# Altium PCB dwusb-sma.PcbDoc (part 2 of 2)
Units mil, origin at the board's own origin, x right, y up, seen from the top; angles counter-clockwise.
Board outline 1415 x 748.03 mil, 4 copper layers (Component Side, Ground Plane, Power Plane, Solder Side), stack 62.214 mil thick; 104 components, 67 nets, 356 pads, 248 vias.
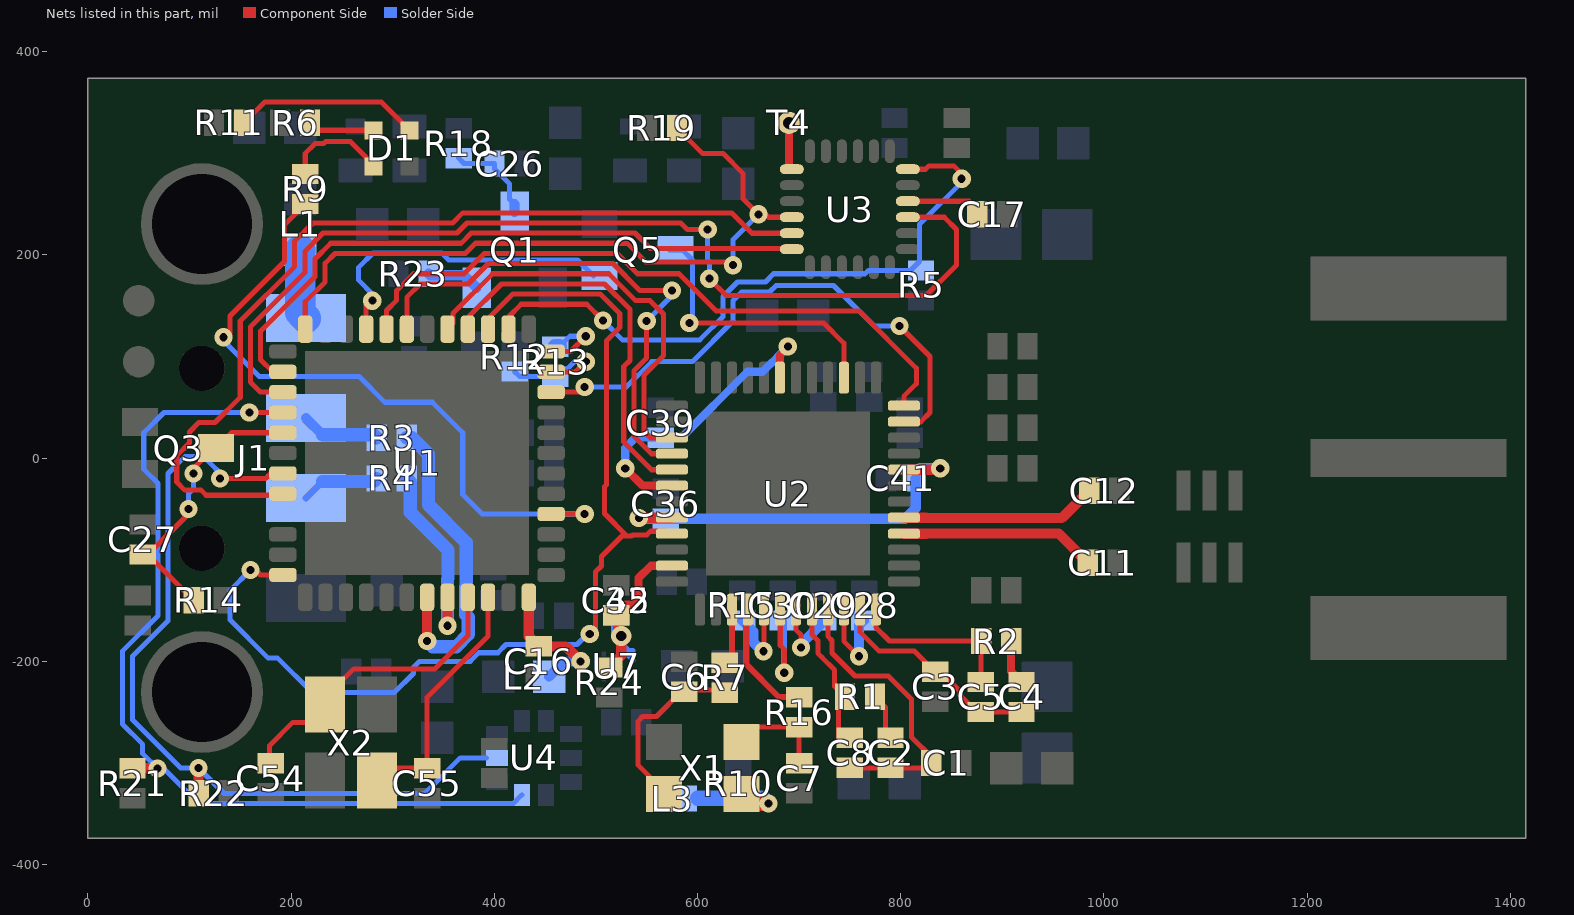
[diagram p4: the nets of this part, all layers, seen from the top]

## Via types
v1: diameter 18, hole 8, Component Side to Solder Side, tented both sides, 165 vias
v2: diameter 18, hole 8, Component Side to Solder Side, 78 vias
v3: diameter 20, hole 10, Component Side to Solder Side, tented both sides, 2 vias
v4: diameter 25, hole 12, Component Side to Solder Side, 2 vias
v5: diameter 22, hole 10, Component Side to Solder Side, tented both sides, 1 vias

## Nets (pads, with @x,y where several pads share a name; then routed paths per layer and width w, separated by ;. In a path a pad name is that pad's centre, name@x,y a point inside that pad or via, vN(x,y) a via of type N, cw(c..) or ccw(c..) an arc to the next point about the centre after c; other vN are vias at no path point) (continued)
LPS25-SCL: R21.1 U1.28 U4.2 | length 922.4
  Component Side w5: v1(68.52,-305.42) v1@68.7,-305.24 ; v1(158.94,45) U1.28@191.94,45 ; v1@68.7,-305.24 68.94,-305 73.94,-305 73.7,-305.24 v1@68.7,-305.24
  Component Side w10: R21.1@43.94,-305.24 v1@68.7,-305.24
  Solder Side w5: v1(158.94,45) 75,45 55,25 55,-10.86 68.94,-24.79 68.94,-155 33.94,-190 33.94,-261.65 53.94,-281.65 53.94,-290.84 v1(68.52,-305.42) 74.56,-305.42 109.14,-340 418.54,-340 U4.2@427.13,-331.42
LPS25-SDA: R22.1 U1.31 U4.4 | length 859.1
  Component Side w5: v2(130,-20) 175,-20 ; 148.94,-20 175,-20 ; 175,-20 177.22,-17.78 ; 177.22,-17.78 189.16,-17.78 U1.31@191.94,-15 180,-15 177.22,-17.78
  Component Side w10: v1(108.94,-305) 108.94,-329.76 R22.1@109.17,-330
  Solder Side w5: v2(130,-20) 135.56,-20 115.56,0 112.27,0 110.77,1.5 95.44,1.5 78.94,-15 78.94,-160 43.94,-195 43.94,-257.51 91.43,-305 v1(108.94,-305) 133.94,-330 331.54,-330 366.54,-295 U4.4@392.52,-295
MPU-CS#: R19.1 U1.24 U3.22 | length 714
  Component Side w5: U1.24@213.94,127 213.94,153.94 233.5,173.5 233.5,191.83 243.17,201.5 371.5,201.5 381.5,211.5 530.77,211.5 549.1,193.17 631.83,193.17 v2(635,190) ; R19.1@579.76,325 604.76,300 625,300 645,280 645,255 v2(660,240) ; v2@663.5,243.5 669.87,237.13 U3.22@692.91,237.13
  Solder Side w5: v2(635,190) 635,215 v2(660,240)
MPU-INT: R5.1 U1.14 U3.12 | length 640.3
  Component Side w5: U1.14@413.94,127 413.94,138.94 426.5,151.5 491.03,151.5 v2@506.5,136.03 ; U3.12@807.09,284.37 824.37,284.37 827.74,287.74 852.26,287.74 860,280 v2(860,275)
  Solder Side w5: v2(507,135.53) 526.03,116.5 602.36,116.5 625,139.14 625,159.14 639.36,173.5 666.83,173.5 674.83,181.5 765,181.5 768.26,184.76 809.76,184.76 818.5,193.5 818.5,230.17 860,271.67 v2(860,275)
MPU-SCK: U1.32 U3.23 | length 914.2
  Component Side w5: U1.32@191.94,-35 190.44,-36.5 116.5,-36.5 111.5,-31.5 95.44,-31.5 87.44,-23.5 87.44,2.44 100,15 100,25.76 109.24,35 125,35 149.94,59.94 149.94,134.94 203.5,188.5 203.5,213.5 221.5,231.5 359.07,231.5 369.07,241.5 633.5,241.5 653.62,221.38 U3.23@692.91,221.38
MPU-SDI: U1.26 U3.24 | length 635.2
  Component Side w5: U1.26@191.94,85 181.88,85 169.94,96.94 169.94,124.94 223.5,178.5 223.5,195.98 239.02,211.5 367.36,211.5 377.36,221.5 538.5,221.5 553.5,206.5 692.91,206.5 U3.24@692.91,205.63
MPU-SDO: U1.27 U3.9 | length 997.2
  Component Side w5: U1.27@191.94,65 170,65 159.94,75.06 159.94,129.08 213.5,182.64 213.5,203.5 231.5,221.5 363.22,221.5 373.22,231.5 583.5,231.5 590,225 v2(610,225) ; v2(611.67,176.67) 628.33,160 825,160 855,190 855,225 842.87,237.13 U3.9@807.09,237.13
  Solder Side w5: v2(610,225) 610,195 611.67,193.33 v2(611.67,176.67)
NetC2_2: C2.2 R1.2 | length 44.5
  Component Side w5: R1.2@774.76,-235 785,-245.24 C2.2@785,-275.24
NetC4_2: C4.2 R2.1 | length 44.5
  Component Side w8: R2.1@908.7,-180 908.7,-210 C4.2@918.94,-220.24
NetC5_2: C5.2 R2.2 U2.12 | length 166.9
  Component Side w5: U2.12@775.55,-149.17 775.55,-166.61 788.94,-180 R2.2@879.17,-180 878.94,-180.24 C5.2@878.94,-220.24
NetC6_2: C6.2 R7.2 X1.3 | length 182.3
  Component Side w5: X1.3@566.81,-330.59 566.81,-327.35 541.59,-302.14 541.59,-258.59 545.99,-254.19 559.57,-254.19 584,-229.76 C6.2@587,-229.76 588,-230.76 595.67,-230.76 598.17,-228.26 624.5,-228.26 R7.2@627,-230.76
NetC7_2: C7.2 R16.2 X1.1 | length 103.6
  Component Side w5: X1.1@638.19,-280 653.43,-264.76 R16.2@700,-264.76 C7.2@700,-300.24
NetC8_1: C8.1 R1.1 U2.8 | length 139.4
  Component Side w5: U2.8@712.56,-149.17 712.56,-173.62 718.44,-179.5 718.44,-191.98 722.44,-195.98 735,-208.54 735,-224.76 R1.1@745.24,-235 ; C8.1@738.94,-275.24 R1.1@738.94,-235.24
NetC17_1: C17.1 U3.10 | length 78.5
  Component Side w5: U3.10@807.09,252.87 867.36,252.87 C17.1@880.24,240
NetC26_1: C26.1 Q1.3 R18.2 | length 93.2
  Solder Side w5: R18.2@365,295.24 370.24,290 C26.1@400.24,290 400.24,284.76 415,270 415,255 Q1.3@420,250
  Solder Side w10: Q1.3@420,242.4 Q1.3@420,250
NetD1_2: D1.2 R9.2 | length 103.2
  Component Side w5: R9.2@213.94,279.76 213.94,300 223.44,309.5 231.81,309.5 233.81,311.5 258.5,311.5 281.22,288.78 D1.2@281.22,287.28
NetD1_3: D1.3 R6.2 | length 54.8
  Component Side w5: R6.2@226.42,322.72 D1.3@281.22,322.72
NetD1_4: D1.4 R11.2 | length 183
  Component Side w5: R11.2@153.7,330 174.2,350.5 288.87,350.5 D1.4@316.65,322.72
NetL3_2: L3.2 R10.2 X1.4 | length 102.9
  Component Side w15: X1.4@643.19,-330.59 645.59,-330.59 655,-340 v1(670,-340)
  Solder Side w15: 600,-334.76 R10.2@640,-334.76 664.76,-334.76 v1(670,-340)
NetQ1_2: Q1.2 R23.2 | length 55.1
  Solder Side w5: R23.2@334.76,180 R23.2@336.7,180
  Solder Side w10: R23.2@335.2,181.5 336.7,180 370.2,180 Q1.2@382.6,167.6
NetR15_2: R15.2 U2.5 | length 83.3
  Component Side w5: v2(665,-190) 665,-191.06 665.32,-191.38 U2.5@665.32,-149.17
  Solder Side w10: R15.2@643.94,-159.76 655,-170.83 655,-181.06 663.94,-190 v2(665,-190)
NetT4_1: T4.1 U3.19 | length 46.8
  Component Side w8: T4.1@690,330 690,287.28 U3.19@692.91,284.37
RED-LED: R9.1 U1.4 | length 666
  Component Side w5: v2(133.44,118.97) 135,117.41 139.94,122.34 139.94,139.94 193.5,193.5 193.5,229.8 R9.1@213.94,250.24 ; U1.4@455.94,-55 v2(488.94,-55)
  Solder Side w5: v2(133.44,118.97) 133.44,115.5 168.44,80.49 266.83,80.49 292.32,55 338.94,55 368.94,25 368.94,-35.86 388.08,-55 v2(488.94,-55)
RESET#: Q5.3 U2.27 | length 284.3
  Component Side w5: v1(592,133) 724.27,133 744.06,113.22 U2.27@744.06,79.17
  Solder Side w5: Q5.3@572.4,205 585,205 595,195 595,136 v1(592,133)
RF-CS#: U1.20 U2.24 | length 657.6
  Component Side w5: U1.20@293.94,127 293.94,145.36 303.94,155.36 303.94,165 320.44,181.5 370.1,181.5 390.1,201.5 520.93,201.5 540.93,181.5 581.83,181.5 618.33,145 758.94,145 815.44,88.5 815.44,73.17 803.11,60.84 U2.24@803.11,51.61
RF-IRQ: U1.15 U1.36 U2.45 | length 1055.6
  Component Side w5: v2(160,-110) 165,-110 170,-115 U1.36@191.94,-115 ; U1.15@393.94,127 393.94,137.37 418.07,161.5 504.36,161.5 523.5,142.36 523.5,128.69 510.44,115.63 510.44,-26.23 508.5,-28.17 508.5,-54.56 530.44,-76.5 ; v2(494,-173) 497,-173 498,-172 499.5,-170.5 499.5,-112.13 505.44,-106.19 505.44,-96.83 525.77,-76.5 530.44,-76.5 ; U2.45@569.76,-74.37 567.31,-71.92 553.69,-71.92 550.11,-75.5 546.45,-75.5 536.09,-75.5 535.09,-76.5 530.44,-76.5
  Solder Side w5: v2(160,-110) 140,-130 140,-159.4 177.1,-196.5 186.5,-196.5 220.5,-230.5 301.81,-230.5 320.44,-211.87 320.44,-205.89 326.33,-200 376.33,-200 384.83,-191.5 403.5,-191.5 411.5,-183.5 481.5,-183.5 494,-171 v2(494,-173)
RF-MISO: U1.19 U2.40 | length 515.5
  Component Side w5: U1.19@313.94,127 313.94,158.33 327.1,171.5 374.24,171.5 394.24,191.5 516.79,191.5 543.29,165 v2(575,165) ; v2(550,135) 550,98.54 537.44,85.98 537.44,21.61 554.68,4.37 U2.40@569.76,4.37
  Solder Side w5: v2(550,135) 575,160 v2(575,165)
RF-MOSI: U1.17 U2.39 | length 410.7
  Component Side w5: U1.17@353.94,127 359.44,132.5 359.44,142.56 398.38,181.5 512.65,181.5 539.15,155 553.33,155 566.5,141.83 566.5,100.9 547.44,81.83 547.44,26.5 553.82,20.12 U2.39@574.76,20.12
RF-RESET: Q5.1 U1.21 | length 308.8
  Component Side w5: U1.21@273.94,127 v1@273.94,150 ; v1@278.94,155 v1(280,155)
  Solder Side w5: v1(280,155) 280,161.67 266.5,175.17 266.5,187.83 280.67,202 348.31,202 355.21,195.1 481.91,195.1 Q5.1@497.6,179.41
RF-SCLK: U1.16 U2.41 | length 381.8
  Component Side w5: U1.16@373.94,127 373.94,138.44 407,171.5 508.5,171.5 533.5,146.5 533.5,96.18 527.44,90.12 527.44,15.86 554.68,-11.38 U2.41@569.76,-11.38
RF-WAKE-UP: U1.10 U2.23 | length 541.8
  Component Side w5: U1.10@455.94,65 483.94,65 v2(488.94,70) ; v2(798.94,130) 828.94,100 828.94,45 819.8,35.87 U2.23@803.11,35.87
  Solder Side w5: v2(488.94,70) 530,70 555,95 595,95 635,135 635,155 643.5,163.5 670.98,163.5 677.48,170 733.94,170 773.94,130 v2(798.94,130)
RF_N: C12.1 U2.17 | length 193.7
  Component Side w9.96: U2.17@803.11,-58.62 825,-58.62 825.39,-59.02 958.46,-59.02 C12.1@985.47,-32.01
RF_P: C11.1 U2.16 | length 193.2
  Component Side w9.96: U2.16@803.11,-74.37 825,-74.37 825.39,-73.98 955.28,-73.98 C11.1@984.17,-102.87
SAM-RESET#: C27.1 Q3.3 R14.1 U1.29 | length 264.7
  Component Side w5: v2@98.94,-55 59.17,-94.76 59.17,-95 R14.1@104.17,-140 ; v1(103.94,-15) 103.94,-10 123.94,10 Q3.3@126.34,10 141.34,25 U1.29@191.94,25
  Solder Side w5: v2(98.94,-50) 98.94,-35 103.94,-30 v1(103.94,-15)
USB-DATA_N: J1.2 R3.2 | length 77.6
  Solder Side w10: J1.2@214.57,39.37 J1.2@230.94,23
  Solder Side w13.07: J1.2@230.94,23 281.17,23 R3.2@284.17,20
USB-DATA_P: J1.3 R4.2 | length 77.6
  Solder Side w7: J1.3@214.57,-39.37 J1.3@230.94,-23
  Solder Side w13.07: J1.3@230.94,-23 281.17,-23 R4.2@284.17,-20
USB_N: R3.1 U1.43 | length 313
  Component Side w10: v2(333.94,-180) U1.43@333.94,-137
  Solder Side w13.07: R3.1@313.7,20 319,20 335.24,3.76 335.24,-45.74 372.54,-83.05 372.54,-125.95 372.01,-126.48 372.01,-154.03 374.47,-156.49 374.47,-173.51 362.44,-185.54 339.47,-185.54 v2(333.94,-180)
USB_P: R4.1 U1.44 | length 190.1
  Component Side w10: v1(353.94,-165) U1.44@353.94,-137
  Solder Side w13.07: R4.1@313.7,-20 317.17,-23.47 317.17,-53.23 354.47,-90.53 354.47,-118.47 353.94,-119 v1(353.94,-165)
VDDBATT: C35.1 C42.1 R24.2 U2.47 U7.1 | length 201.7
  Component Side w8: C35.1@522,-156.76 522,-150.76 528.53,-144.24 536.73,-144.24 541.36,-139.6 542,-138.96 542,-118 554.13,-105.87 U2.47@574.76,-105.87
  Component Side w10: R24.2@513.31,-205.98 525,-194.29 v3(525,-175) v3@520.24,-175 ; v3@520,-174.76 522,-176.76 522,-156.76 C35.1@520,-154.76
  Solder Side w8: v3(525,-175) 525,-184.25 530,-189.25 530,-190.39 U7.1@532.3,-192.7
  Solder Side w10: C42.1@520,-154.76 520,-174.76 520.24,-175 v3(525,-175)
VDDCLK: C1.2 C2.1 C8.2 U2.9 | length 299.5
  Component Side w5: U2.9@728.31,-149.17 728.31,-175.23 732.44,-179.36 732.44,-191.83 755.1,-214.5 787.87,-214.5 810.5,-237.13 810.5,-274.45 830.24,-294.19 C1.2@830.24,-300 825.47,-304.76 C2.1@790,-304.76 C8.2@750,-304.76 C8.2@745,-304.76
VDDIF: C29.1 U2.7 | length 75
  Component Side w5: U2.7@696.81,-149.17 696.81,-168.81 701.94,-173.94 v2(701.94,-186.33)
  Solder Side w5: C29.1@723.94,-161.06 C29.1@723.94,-159.76
  Solder Side w10: v2(701.94,-186.33) 701.94,-183.06 C29.1@723.94,-161.06
VDDIO: C39.1 U2.31 U2.42 | length 303.7
  Component Side w8: v2(528.94,-10) 545.94,-27 569.64,-27 U2.42@569.76,-27.13 ; U2.31@681.06,79.17 681.06,101.67 688.94,109.54 v1(688.94,110)
  Solder Side w8: v2(528.94,-10) 528.94,10 539.17,20.24 C39.1@563.94,20.24 584.17,20.24 648.94,85 663.94,85 672.32,93.38 672.77,93.38 683.32,103.92 683.32,104.38 v1(688.94,110)
VDDMS: C30.1 U2.6 | length 116.7
  Component Side w5: U2.6@681.06,-149.17 681.5,-149.61 681.5,-184.23 685.44,-188.17 v2(685.44,-211.24)
  Solder Side w5: C30.1@683.94,-159.76 685.2,-159.76 685.44,-160 v2(685.44,-211.24)
VDDPLL: C16.1 L2.2 U1.48 | length 136.8
  Component Side w10: U1.48@433.94,-137 433.94,-175.24 C16.1@443.94,-185.24 470.24,-185.24 v2(485,-200)
  Solder Side w10: L2.2@453.94,-215 468.94,-200 v2(485,-200)
VDDREG: C36.1 C41.1 U2.20 U2.44 | length 412.3
  Component Side w10: v1(542.27,-59) 539.94,-59 539.33,-59.61 540.32,-58.62 U2.44@574.76,-58.62 ; U2.20@803.11,-11.38 837.56,-11.38 v1(838.94,-10)
  Solder Side w10: v1(542.27,-59) 542.88,-59.61 803.54,-59.61 803.94,-60 814.76,-49.17 C41.1@814.76,-20 ; C41.1@817.87,-20 817.87,-11.38 819.25,-10 v1(838.94,-10)
VDDSYN: C28.1 U2.10 | length 89.3
  Component Side w5: U2.10@744.06,-149.17 744.06,-180.12 v2(758.94,-195)
  Solder Side w10: v2(758.94,-195) 758.94,-164.76 C28.1@763.94,-159.76
VDDVCO: C3.1 C4.1 C5.1 U2.11 | length 215.8
  Component Side w5: U2.11@759.8,-149.17 759.8,-170.87 778.94,-190 813.7,-190 C3.1@833.94,-210.24 839.17,-210.24 858.44,-229.5 858.44,-233.34 874.86,-249.76 C5.1@878.94,-249.76 C4.1@918.94,-249.76
VERSION-SENSE: R12.1 R13.2 U1.11 | length 116.4
  Component Side w5: U1.11@455.94,85 480,85 v2(490,95)
  Solder Side w5: R12.1@420,85.24 425,80.24 R13.2@460,80.24 464.08,80.24 478.84,95 v2(490,95)
VERSION-SENSE-EN#: R13.1 U1.12 | length 74.5
  Component Side w5: U1.12@455.94,105 475,105 v2(490,120)
  Solder Side w5: R13.1@464.11,109.76 474.34,120 v2(490,120)
  Solder Side w15: R13.1@460,109.76 R13.1@464.11,109.76
VIN: J1.1 L1.1 | length 69.5
  Solder Side w30: L1.1@208.94,205 208.94,143.42 J1.1@214.57,137.8
XIN: C55.1 U1.46 X2.1 | length 247.5
  Component Side w5: X2.1@284.53,-317.4 296.69,-305.24 C55.1@333.94,-305.24 333.94,-235 393.94,-175 U1.46@393.94,-137
XOUT: C54.1 U1.45 X2.3 | length 294
  Component Side w5: C54.1@178.94,-295.24 178.94,-282.8 201.74,-260 215.94,-260 X2.3@233.35,-242.6 233.35,-235.93 261.74,-207.54 341.4,-207.54 373.94,-175 U1.45@373.94,-137
XTAL1: R7.1 U2.3 | length 62.5
  Component Side w6: R7.1@619.7,-200.3 629.11,-200.3 633.82,-195.59 U2.3@633.82,-149.17
XTAL2: R16.1 U2.4 | length 119.8
  Component Side w6: U2.4@649.57,-149.17 648,-150.74 648,-203 680.24,-235.24 R16.1@700,-235.24
pads on no net: J1. U1.5 U1.6 U1.22 U1.25 U1.35 U1.37 U1.38 U1.39 U1.40 U2.1 U2.2 U2.13 U2.14 U2.29 U2.30 U2.33 U2.34 U2.35 U2.36 U2.37 U2.38 U3.2 U3.3 U3.4 U3.5 U3.6 U3.7 U3.14 U3.15 U3.16 U3.17 U3.21 Z1.6

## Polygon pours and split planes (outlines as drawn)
GND on Solder Side "Bottom Overlay-No Net" (solid, pour order 7): 1398.49,347 27.51,347 27.51,-353 1398.49,-353
GND on Component Side "top-ground" (solid, remove dead copper, pour order 3): 1394.96,-352.09 25.79,-352.09 25.79,347.91 1394.96,347.91
GND on Ground Plane (split plane): 1394.9,-353.92 713.02,-353.92 713.02,-230 712.7,-228.44 711.82,-227.12 710.5,-226.23 708.94,-225.92 707.38,-226.23 706.05,-227.12 705.17,-228.44 704.86,-230 704.86,-353.92 504.08,-353.92 504.08,-206.06 503.77,-204.5 502.88,-203.18 501.56,-202.3 500,-201.98 498.44,-202.3 497.12,-203.18 496.23,-204.5 495.92,-206.06 495.92,-353.92 20.1,-353.92 20.1,353.92 1394.9,353.92
1V8 on Power Plane (split plane): 640.92,278.31 640.92,246.69 623.04,228.81 622.15,227.48 621.84,225.92 621.84,175 622.15,173.44 623.04,172.12 624.36,171.23 625.92,170.92 747.25,170.92 779.86,138.31 779.86,-34.37 638.31,-175.92 544.08,-175.92 544.08,-105.63 741.82,92.12 742.7,93.44 743.02,95 743.02,115 742.7,116.56 741.82,117.88 731.82,127.88 730.5,128.77 728.94,129.08 576.69,129.08 539.08,166.69 539.08,223.31 572.88,257.12 606.69,290.92 628.31,290.92
GND on Power Plane (split plane): 1394.9,-353.92 1105,-353.92 1105,-315 1035,-315 1035,-353.92 1023.31,-353.92 1023.31,353.92 1394.9,353.92
1V2 on Power Plane (split plane): 360.92,65 361.23,63.44 362.12,62.12 363.44,61.23 365,60.92 514.86,60.92 514.86,9.08 482,9.08 480.44,8.77 479.12,7.88 396.05,-75.18 395.17,-76.5 394.86,-78.06 394.86,-229.37 378.31,-245.92 308.69,-245.92 278.02,-215.25 278.02,-61 277.7,-59.44 276.82,-58.12 275.5,-57.23 273.94,-56.92 207.08,-56.92 207.08,61.92 273.94,61.92 275.5,62.23 276.82,63.12 277.7,64.44 278.02,66 278.02,170.92 360.92,170.92
3V3 on Power Plane (split plane): 1008.18,-353.92 713.02,-353.92 713.02,-229.02 712.7,-227.45 711.82,-226.13 710.5,-225.25 708.94,-224.94 707.38,-225.25 706.05,-226.13 705.17,-227.45 704.86,-229.02 704.86,-353.92 524.08,-353.92 524.08,-205.08 523.77,-203.52 522.88,-202.19 521.56,-201.31 520,-201 518.44,-201.31 517.12,-202.19 516.23,-203.52 515.92,-205.08 515.92,-353.92 20.1,-353.92 20.1,353.92 1008.18,353.92

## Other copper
Component Side:
  rectangle net VDDBATT: 515,-189 531,-160
  rectangle net GND: 695,-350 735,-325
  rectangle net GND: 680,-325 695,-320
  rectangle net GND: 670,-325 680,-275
  rectangle net GND: 580.26,-260 580.79,-246.69
  rectangle net GND: 580.79,-260 605,-247.77
  rectangle net GND: 295,-260 325,-240
  rectangle net 3V3: 795,-45 881,-26
  rectangle net BAL_P: 1003,-120 1085,-84.78
  rectangle net BAL_N: 1004.3,-50.71 1085,-13.31
  rectangle net ANTENNA: 1130,-50.71 1150,-13.31
  rectangle net GND: 928.7,-143.66 948.94,-115
  rectangle net 3V3: 305,250 340,295
  rectangle net 3V3: 305,250 390,295
  rectangle net 3V3: 883.94,-15 895.24,110
  rectangle net 3V3: 875,-22.38 895.24,35
  rectangle net 3V3: 875,30 895.24,60
  pour cut-out: 550,-260 550,-345 662,-345 662,-260
  pour cut-out: 469.9,-79.93 469.9,-101.46 489.38,-120.94 496.8,-120.94 496.8,-81.28 497.14,-80.94
  pour cut-out: 84.47,19.47 112.44,47.44 189.5,47.44 191.94,45 191.94,-35 85.77,-35 85.14,-34.37
  pour cut-out: 797.14,234.89 796.61,199.27 805.89,190 830,190 830,235
  pour cut-out: 655,350 655,290 790,290 790,350
  pour cut-out: 575,123 573.94,-146.17 798.94,-146.17 795,123
  pour cut-out: 1105,-355 1105,-275 1035,-275 1035,-355
  pour cut-out: 210,-355 210,-340 145,-340 145,-355
  pour cut-out: 190,-268 190,-293 209.62,-293 210.8,-294.18 212,-292.98 212,-267
Solder Side:
  rectangle net VDDBATT: 520,-175 530,-154.76
  rectangle net GND: 645,-230 656,-215
  rectangle net GND: 635,-240 645,-215
  rectangle net GND: 460,-290 490,-275
  rectangle net GND: 301.81,-260 322.94,-238.15
  rectangle net 1V8: 580,255 626,287
  rectangle net GND: 610,310 666,355
  region net GND: 550,254 550,305 449.25,305 449.25,254
  rectangle net GND: 235,210 285,300
  rectangle net GND: 943.94,170 983.94,200
  rectangle net 3V3: 873.94,170 913.94,200
  region net GND: 988.94,-245 988.94,-205 958.94,-205 958.94,-245
  region net 3V3: 993.94,-315 993.94,-275 963.94,-275 963.94,-315
  rectangle net 3V3: 305,240 385,275
  rectangle net GND: 305,72.65 395,95
  rectangle net GND: 296.91,76.15 357,100.24
  rectangle net 3V3: 444.82,-325 468.98,-315.81
  rectangle net GND: 520,-120.24 543,-92.09
  pour cut-out: 470,310 580,310 580,255 470,255
  pour cut-out: 425,305 425,280 430,240 453.5,240 453.5,305 445,305
  pour cut-out: 520,-205 520,-240 536.76,-240 544.67,-232.1 544.67,-204.94
  pour cut-out: 170,320 170,191.93 171.04,190.89 265.6,190.89 265.6,319.4 265,320
  pour cut-out: 420,-30 420,50 355,50 355,-30
  pour cut-out: 540,-60 525,-60 525,-25 540,-25
  pour cut-out: 275,20 275,-20 175,-20 175,20
  pour cut-out: 1105,-355 1105,-275 1035,-275 1035,-355
  pour cut-out: 384.3,-85 384.3,-90.24 384.3,-115.24 421.94,-115.24 421.94,-105.24 421.94,-90.24 420,-85
Ground Plane (plane layer: these items are gaps in the copper):
  region: 1105,-275 1035,-275 1035,-315 1105,-315
  lines w8: 500,-375 500,-206.06 ; 500,-360.08 513.94,-374.02 ; 708.94,-374.02 708.94,-230
  text "2" at 1090,-345 h35 r90
Power Plane (plane layer: these items are gaps in the copper):
  rectangle: 1035,-355 1105,-315
  lines w5: 3.94,-80 3.94,-40
  lines w8: 520,-374.02 520,-205.08 ; 708.94,-373.03 708.94,-229.02 ; 203,-61 203,66 273.94,66 273.94,175 313.94,175 365,175 365,65 518.94,65 518.94,5 482,5 398.94,-78.06 398.94,-231.06 380,-250 307,-250 273.94,-216.94 273.94,-61 203,-61 ; 535,165 535,225 570,260 605,295 630,295 645,280 645,245 625.92,225.92 625.92,175 748.94,175 783.94,140 783.94,-36.06 640,-180 540,-180 540,-103.94 738.94,95 738.94,115 728.94,125 575,125 535,165
  lines w15: 1015.75,-386.1 1015.75,386.1
  text "3" at 1090,-305 h35 r90

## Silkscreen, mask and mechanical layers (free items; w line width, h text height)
Top Overlay:
  rectangle: 1355,220 1400,255
  lines w6: 967.74,-28.26 967.74,-12.01 ; 983,-83 995,-83
  lines w8: 833.94,-180 833.94,-92.06 ; 833.94,-37.94 833.94,110 ; 1190,58 1190,215 ; 1035,-365 1105,-365 1105,-270 1035,-270 1035,-365
  text "C" at 1121,315 h35.43
  text "DWUSB-SMA" at 1150,260 h28
  text "1.1." at 1300,225 h25
  text "Erase" at 45,190 h18 r90
  text "B" at 955,147.99 h300
  text ".VErsionControl_RevNumber" at 1235,-350 h30
Bottom Overlay:
  lines w8: 446,313 446,355 ; 1035,-365 1105,-365 1105,-270 1035,-270 1035,-365
  text "D" at 1394.68,127.95 h400 r90
Top Solder:
  rectangle: 1145,-55 1195,25
  rectangle: 1035,-125 1065,-10
  rectangle: 840,-82 965,-51
Board:
  the board outline again, w8
Fabrication Drawing:
  drawing of 358 lines, arcs and shapes, not listed
  text "A" at -1450,8650 h125
  text "B" at -500,8650 h125
  text "C" at 450,8650 h125
  text "D" at 1500,8650 h125
  text "E" at 2475,8650 h125
  text "F" at 3500,8650 h125
  text "G" at 4500,8650 h125
  text "H" at 5475,8650 h125
  text "I" at 6500,8650 h125
  text "J" at 7525,8650 h125
  text "K" at 8500,8650 h125
  text "L" at 9525,8650 h125
  text "M" at 10500,8650 h125
  text "N" at 11475,8650 h125
  text "O" at 12500,8650 h125
  text "P" at 13525,8650 h125
  text "Q" at 14500,8650 h125
  text "11" at -1950,8275 h125
  text "11" at 14825,8275 h125
  text "10" at -1975,7275 h125
  text "10" at 14800,7275 h125
  text "9" at -1925,6250 h125
  text "9" at 14850,6250 h125
  text "8" at -1925,5250 h125
  text "8" at 14850,5250 h125
  text "7" at -1925,4250 h125
  text "7" at 14850,4250 h125
  text "6" at -1925,3250 h125
  text "6" at 14850,3250 h125
  text "5" at -1925,2250 h125
  text "5" at 14850,2250 h125
  text "Layer" at -1381.3,1822.5 h60
  text "Name" at -971.39,1822.5 h60
  text "Material" at -31.65,1822.5 h60
  text "Thickness" at 828.12,1822.5 h60
  text "Constant" at 1477.96,1822.5 h60
  text "Board Layer Stack" at 2047.82,1822.5 h60
  text "1" at -1381.3,1702.5 h60
  text "Top Overlay" at -971.39,1702.5 h60
  text "2" at -1381.3,1582.5 h60
  text "Top Solder" at -971.39,1582.5 h60
  text "Solder Resist" at -31.65,1582.5 h60
  text "0.40mil" at 828.12,1582.5 h60
  text "3.5" at 1477.96,1582.5 h60
  text "3" at -1381.3,1462.5 h60
  text "Component Side" at -971.39,1462.5 h60
  text "Copper" at -31.65,1462.5 h60
  text "1.40mil" at 828.12,1462.5 h60
  text "4" at -1381.3,1342.5 h60
  text "Dielectric1" at -971.39,1342.5 h60
  text "FR-4" at -31.65,1342.5 h60
  text "20.08mil" at 828.12,1342.5 h60
  text "4.5" at 1477.96,1342.5 h60
  text "4" at -1925,1250 h125
  text "4" at 14850,1250 h125
  text "5" at -1381.3,1222.5 h60
  text "Ground Plane" at -971.39,1222.5 h60
  text "Copper" at -31.65,1222.5 h60
  text "1.40mil" at 828.12,1222.5 h60
  text "6" at -1381.3,1102.5 h60
  text "Dielectric2" at -971.39,1102.5 h60
  text "FR-4" at -31.65,1102.5 h60
  text "16.46mil" at 828.12,1102.5 h60
  text "4.5" at 1477.96,1102.5 h60
  text "7" at -1381.3,982.5 h60
  text "Power Plane" at -971.39,982.5 h60
  text "Copper" at -31.65,982.5 h60
  text "1.40mil" at 828.12,982.5 h60
  text "1.6mm +- 10% finished board thickness" at 3355,930 h100
  text "8" at -1381.3,862.5 h60
  text "Dielectric3" at -971.39,862.5 h60
  text "FR-4" at -31.65,862.5 h60
  text "20.08mil" at 828.12,862.5 h60
  text "4.5" at 1477.96,862.5 h60
  text "CONTROLLED IMPEDANCE" at 3350,785 h100
  text "9" at -1381.3,742.5 h60
  text "Solder Side" at -971.39,742.5 h60
  text "Copper" at -31.65,742.5 h60
  text "1.40mil" at 828.12,742.5 h60
  text "50 ohm +-10% single-ended impedance, top layer; 0.95mm wide" at 3355,655 h50
  text "10" at -1381.3,622.5 h60
  text "Bottom Solder" at -971.39,622.5 h60
  text "Solder Resist" at -31.65,622.5 h60
  text "0.40mil" at 828.12,622.5 h60
  text "3.5" at 1477.96,622.5 h60
  text "Maintain 1mm separation to top layer ground pour on 50 Ohm traces." at 3580,570 h50
  text "11" at -1381.3,502.5 h60
  text "Bottom Overlay" at -971.39,502.5 h60
  text "100 ohm +-10% differential impedance, top layer; 0.253mm wide 0.127 mm spacing" at 3330,480 h50
  text "1 Oz. Finished Copper" at 3350,320 h60
  text "3" at -1925,250 h125
  text "3" at 14850,250 h125
  text "ENIG or silver immersion pad finish" at 3350,211.25 h60
  text "White Legend Top and Bottom" at 3350,102.5 h60
  text "Do Not Connect to Panel" at 1720,40 h35
  text "Do Not Connect to Panel" at -1000,30 h35
  text "Red Solder Mask Top and Bottom" at 3350,-6.25 h60
  text "Along This Edge" at 1790,-25 h35
  text "Along This Edge" at -930,-35 h35
  text "Fabricate board in a 2 by 5 array" at 3350,-115 h60
  text "with 6.5mm minimum border and 3.5mm tooling holes." at 3350,-223.75 h60
  text "PCB edge remnant from panelization should" at 3350,-332.5 h60
  text "be removed after assembly" at 3350,-441.25 h60
  text "ROHS Compliant FR-4" at 3350,-550 h60
  text "2" at -1925,-750 h125
  text "2" at 14850,-750 h125
  text "1" at -1900,-1650 h125
  text "1" at 14875,-1650 h125
  text "A" at -1500,-2125 h125
  text "B" at -550,-2125 h125
  text "D" at 1450,-2125 h125
  text "E" at 2425,-2125 h125
  text "F" at 3450,-2125 h125
  text "G" at 4450,-2125 h125
  text "H" at 5425,-2125 h125
  text "I" at 6450,-2125 h125
  text "J" at 7475,-2125 h125
  text "K" at 8450,-2125 h125
  text "L" at 9475,-2125 h125
  text "M" at 10450,-2125 h125
  text "N" at 11425,-2125 h125
  text "O" at 12450,-2125 h125
  text "P" at 13475,-2125 h125
  text "Q" at 14450,-2125 h125
Design Information:
  text "Title :" at -905,-715 h100
  text "Engineer :" at 865,-725 h100
  text ".ProjectTitle" at -415,-730 h100
  text ".Engineer" at 1655,-730 h100
  text "Part Number :" at -1580,-865 h100
  text ".PartNumber" at -415,-875 h100
  text ".Email" at 1655,-875 h100
  text "Revision :" at -1190,-1020 h100
  text ".Phone" at 1665,-1025 h100
  text ".ProjectRevision" at -410,-1035 h100
  text ".VErsionControl_RevNumber" at -415,-1175 h100
  text "SVN :" at -855,-1180 h100
  text "(c) 2016 CIHOLAS Inc." at 190,-1390 h100
Drill Drawing:
  circle w10: c3304.75,1660.83 r33.33
  lines w10: 3271.42,1477.5 3338.08,1477.5 3338.08,1544.17 3271.42,1544.17 3271.42,1477.5 ; 3271.42,1844.17 3338.08,1844.17 3304.75,1777.5 3271.42,1844.17 ; 3271.42,1927.5 3304.75,1944.17 3338.08,1927.5 3321.42,1960.83 3338.08,1994.17 3304.75,1977.5 3271.42,1994.17 3288.08,1960.83 3271.42,1927.5 ; 3271.42,2094.17 3288.08,2094.17 3304.75,2077.5 3321.42,2094.17 3338.08,2094.17 3321.42,2110.83 3338.08,2127.5 3321.42,2127.5 3304.75,2144.17 3288.08,2127.5 3271.42,2127.5 3288.08,2110.83 3271.42,2094.17
  lines w15: 3211.62,1432.5 7090.6,1432.5 ; 3211.62,2182.5 7090.6,2182.5 ; 3762.5,1282.5 3762.5,2332.5 ; 4460.31,1282.5 4460.31,2332.5 ; 5805.92,1282.5 5805.92,2332.5 ; 6311.79,1282.5 6311.79,2332.5 ; 3211.62,1282.5 7090.6,1282.5 7090.6,2332.5 3211.62,2332.5 3211.62,1282.5
  text "Symbol" at 3301.62,2227.5 h72
  text "Hit Count" at 3807.5,2227.5 h72
  text "Finished Hole Size" at 4505.31,2227.5 h72
  text "Plated" at 5850.92,2227.5 h72
  text "Hole Type" at 6356.79,2227.5 h72
  text "2" at 3807.5,2077.5 h60
  text "45.00mil (1.143mm)" at 4505.31,2077.5 h60
  text "NPTH" at 5850.92,2077.5 h60
  text "Round" at 6356.79,2077.5 h60
  text "2" at 3807.5,1927.5 h60
  text "98.43mil (2.500mm)" at 4505.31,1927.5 h60
  text "PTH" at 5850.92,1927.5 h60
  text "Round" at 6356.79,1927.5 h60
  text "3" at 3807.5,1777.5 h60
  text "10.00mil (0.254mm)" at 4505.31,1777.5 h60
  text "PTH" at 5850.92,1777.5 h60
  text "Round" at 6356.79,1777.5 h60
  text "3" at 3807.5,1627.5 h60
  text "12.00mil (0.305mm)" at 4505.31,1627.5 h60
  text "PTH" at 5850.92,1627.5 h60
  text "Round" at 6356.79,1627.5 h60
  text "243" at 3807.5,1477.5 h60
  text "8.00mil (0.203mm)" at 4505.31,1477.5 h60
  text "PTH" at 5850.92,1477.5 h60
  text "Round" at 6356.79,1477.5 h60
  text "253 Total" at 3807.5,1327.5 h60
3D Bodies:
  lines w8: 446.5,355 447,355

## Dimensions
0,-374.02 to 1415,-374.02 on Fabrication Drawing
0,374.02 to 0,-374.02 on Fabrication Drawing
